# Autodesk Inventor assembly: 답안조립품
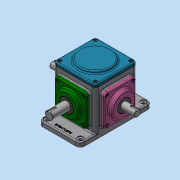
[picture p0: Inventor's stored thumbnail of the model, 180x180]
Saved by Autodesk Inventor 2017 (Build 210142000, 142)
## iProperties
Part Number: 답안조립품
Material: 일반
Document SubType Name: Assembly
Designer: MRC
Author: MRC
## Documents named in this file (16)
- C:\Users\MRC\Desktop\620307V1001\답안조립품.iam
- C:\Users\MRC\Desktop\620307V1001\본체.ipt
- C:\Users\MRC\Desktop\620307V1001\개스킷.ipt
- C:\Users\MRC\Desktop\620307V1001\메인베벨기어.ipt
- C:\Users\MRC\Desktop\620307V1001\메인축.ipt
- C:\Users\MRC\Desktop\620307V1001\메인커버.ipt
- C:\Users\MRC\Desktop\620307V1001\베어링 6203.ipt
- C:\Users\MRC\Desktop\620307V1001\베어링 6204.ipt
- C:\Users\MRC\Desktop\620307V1001\볼트 M4.ipt
- C:\Users\MRC\Desktop\620307V1001\상부커버.ipt
- C:\Users\MRC\Desktop\620307V1001\서브베벨기어.ipt
- C:\Users\MRC\Desktop\620307V1001\서브축.ipt
- C:\Users\MRC\Desktop\620307V1001\서브커버.ipt
- C:\Users\MRC\Desktop\620307V1001\오일 실 17 32 8.ipt
- C:\Users\MRC\Desktop\620307V1001\오일 실 20 35 8.ipt
- C:\Users\MRC\Desktop\620307V1001\키 4x4.ipt
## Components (1 placed, 1 different names)
1. 개스킷:1
